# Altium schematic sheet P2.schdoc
size 297 x 209 mm; Symbol: Drawing-Symbol_A4; @Project Name: New Project_2025-09-22_16-04-54; @Page Count: 2; @Update Date: 2026-01-23; @Create Date: 2025-09-24; @Schematic Name: Schematic1; @Page No: 2; @Page Name: P2; Company: EasyEDA.com; Version: V1.0; Page Size: A4; @Create Time: 09:42:08; @Update Time: 20:37:24; Border: 1; Width: 1170; Height: 825; Region Start: 1; X Region Count: 6; Y Region Count: 4; Blade Width: 10; Title Block Position: 3; @Board Name: Board1; Device: Drawing-Symbol_A4
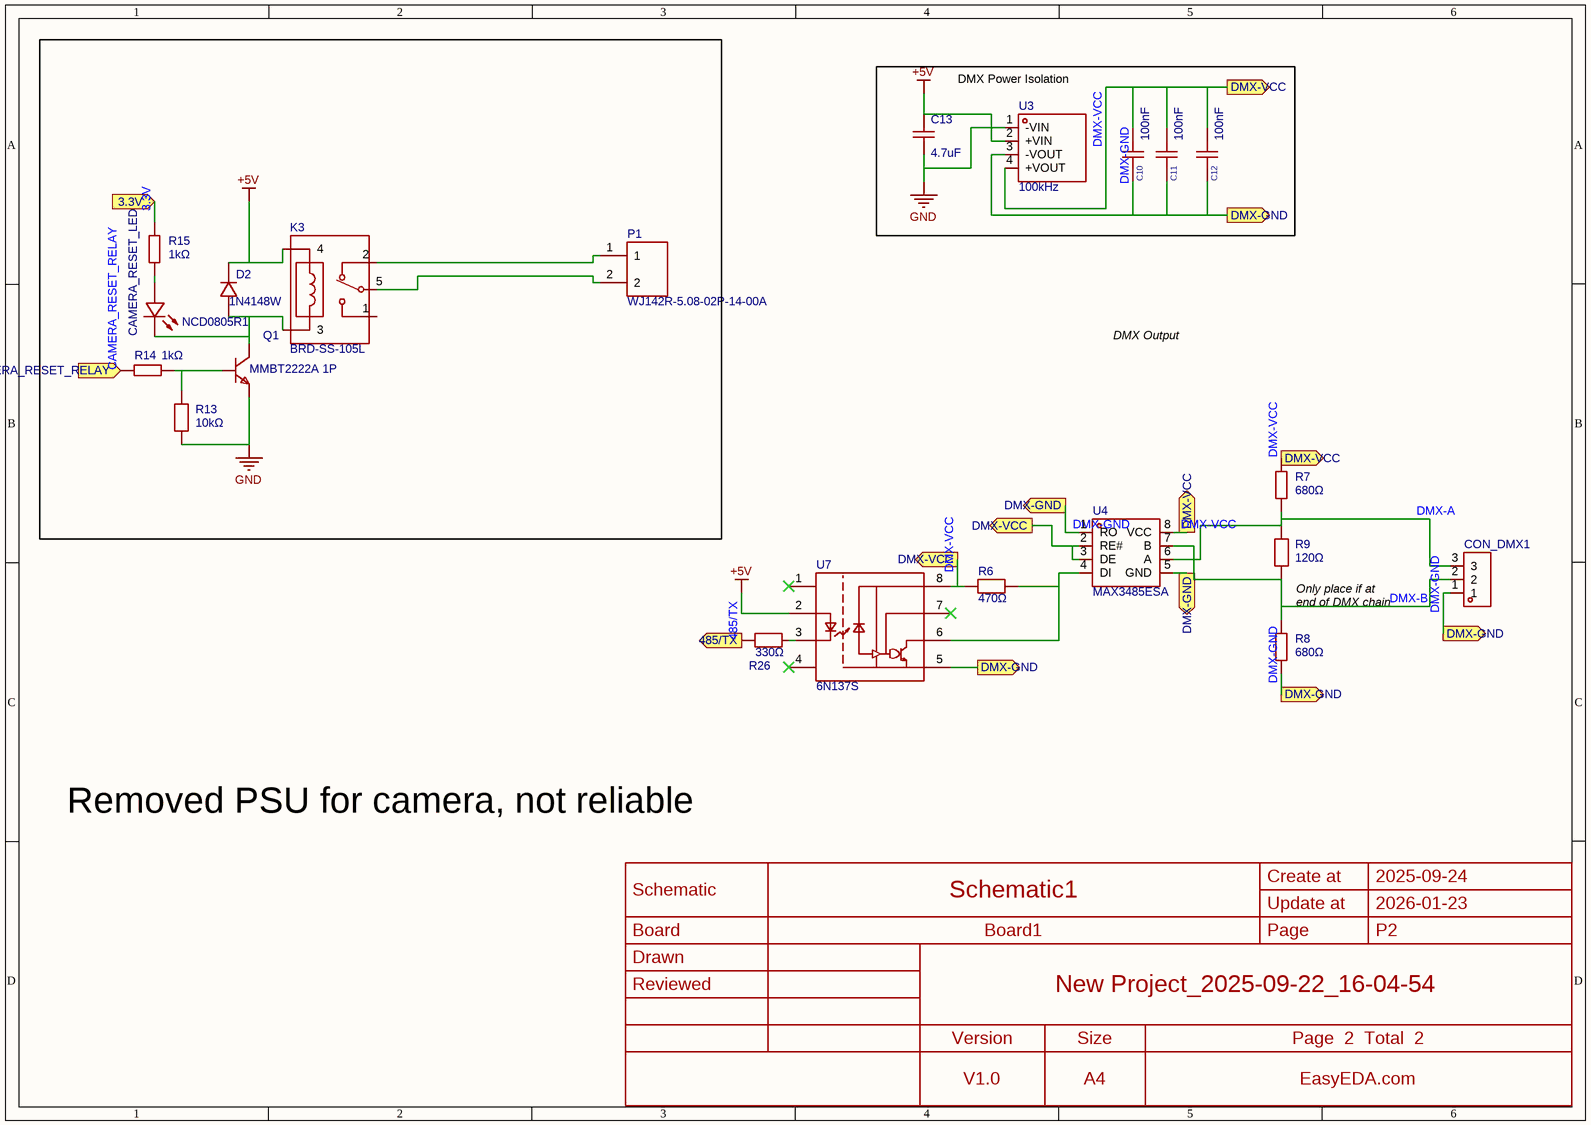
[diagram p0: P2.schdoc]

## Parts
C10  100nF  [C0603]
C11  100nF  [C0603]
C12  100nF  [C0603]
C13  4.7uF  [C0603]
CAMERA_RESET_LED1  NCD0805R1  [LED0805-R-RD]
CON_DMX1  WJ142R-5.08-03P-14-00A  [CONN-TH_3P-P5.08_WJ142R-5.08-3P]  (value not drawn)
D2  1N4148W  [SOD-123F_L2.7-W1.6-LS3.8-RD]
K3  BRD-SS-105L  [RELAY-TH_BRD-SS-1XXL]
P1  WJ142R-5.08-02P-14-00A  [CONN-TH_2P-P5.08_WJ142R-5.08-2P]
Q1  MMBT2222A 1P  [SOT-23-3_L2.9-W1.3-P1.90-LS2.4-BR]
R6  470Ω  [R0603]
R7  680Ω  [R0603]
R8  680Ω  [R0603]
R9  120Ω  [R0603]
R13  10kΩ  [R0603]
R14  1kΩ  [R0603]
R15  1kΩ  [R0603]
R26  330Ω  [R0603]
U3  100kHz  [PWRM-TH_B0505S-1W]
U4  MAX3485ESA  [SOP-8_L4.9-W3.9-P1.27-LS6.0-BL]
U7  6N137S  [SMT-8_L9.7-W6.6-P2.54-LS10.3-BL]

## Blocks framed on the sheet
DMX Power Isolation: C10-C13 U3

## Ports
3.3V (in), 485/TX (out), CAMERA_RESET_RELAY (in), DMX-GND (out), DMX-VCC (out)

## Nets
+5V: C13.1 D2.1(C) K3.4 U3.2(+VIN) U7.2(A)
GND: C13.2 Q1.2(E) R13.1 U3.1(-VIN)
3.3V: R15.2 ; port 3.3V
485/TX: R26.1 ; port 485/TX
CAMERA_RESET_RELAY: R14.1 ; port CAMERA_RESET_RELAY
DMX-A: CON_DMX1.3 R7.1 R9.2 U4.6(A)
DMX-B: CON_DMX1.2 R8.2 R9.1 U4.7(B)
DMX-GND: C10.1 C11.1 C12.1 CON_DMX1.1 R8.1 U3.3(-VOUT) U4.1(RO) U4.5(GND) U7.5(GND) ; port DMX-GND
DMX-VCC: C10.2 C11.2 C12.2 R6.1 R7.2 U3.4(+VOUT) U4.2(RE#) U4.3(DE) U4.8(VCC) U7.8(VCC) ; port DMX-VCC
NetCAMERA_RESET_LED1_1: CAMERA_RESET_LED1.1(+) R15.1
NetCAMERA_RESET_LED1_2: CAMERA_RESET_LED1.2(-) D2.2(A) K3.3 Q1.3(C)
NetK3_2: K3.2 P1.1
NetK3_5: K3.5 P1.2
NetQ1_1: Q1.1(B) R13.2 R14.2
NetR6_2: R6.2 U4.4(DI) U7.6(VO)
NetR26_2: R26.2 U7.3(C)

Not connected (* = marked no-connect by the designer): K3 1; U7 1(NC)* 4(NC)* 7(VE)*

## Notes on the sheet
- DMX Output
- Only place if at
  end of DMX chain
- Removed PSU for camera, not reliable

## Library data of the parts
C10-C12 = CC0603KRX7R9BB104: Capacitance:100nF Tolerance:±10% Tolerance:±10% Voltage Rating:50V Temperature Coefficient:X7R; Manufacturer: YAGEO(国巨); Symbol: CL10B104KB8NNNC; AddInBom: yes; ModelId: 624118aa3cc7497086c383c2d72e0852; ModelName: C0603_L1.6-W0.8-H0.8; ModelTransform: 62.992,31.496,0,0,0,0,0,0,0; Tolerance: ±10%; Voltage Rating: 50V; Temperature Coefficient: X7R
C13 = CL10A475KO8NNNC: Capacitance:4.7uF Tolerance:±10% Tolerance:±10% Voltage Rating:16V Temperature Coefficient:X5R; Manufacturer: SAMSUNG(三星); Symbol: CL10A475KA8NQNC; AddInBom: yes; ModelId: 624118aa3cc7497086c383c2d72e0852; ModelName: C0603_L1.6-W0.8-H0.8; ModelTransform: 62.992,31.496,0,0,0,0,0,0,0; Tolerance: ±10%; Voltage Rating: 16V; Temperature Coefficient: X5R
CAMERA_RESET_LED1 = NCD0805R1_C84256: Lamp Holder Type:- Emitted Color:Red Forward Voltage (VF):1.6V~2.6V Forward Voltage (VF):1.6V~2.6V Power Dissipation:65mW Forward Current:20mA Dominant Wavelength:615nm~630nm Dominant Wavelength:615nm~630nm Peak Wavelength:- Diode Configuration:独立二极管 Lens; Manufacturer: 国星光电; Symbol: FC-2012HRK-620D; AddInBom: yes; ModelId: 167045bb0eae412b9d5564860e113a91; ModelName: LED0805-RD; ModelTransform: 79.527,49.2125,0,0,0,0,0,0,0; Emitted Color: Red; Power Dissipation: 65mW; Forward Current: 20mA; Diode Configuration: 独立二极管; Lens Color: 无色透明透镜; Luminous Intensity: 67mcd~195mcd; Viewing Angle: 130°
CON_DMX1 = WJ142R-5.08-03P-14-00A: Pitch:5.08mm Mounting Type:Through Hole Number of Pins:3P Number of PINs Per Row:3 Number of Rows:1 Current Rating:10A Voltage Rating (Max):300V Wire Gauge - AWG:14~22 Wire Gauge - mm2:1.5 Operating Temperature:-40℃~+105℃ Operating Temperature:-40℃~+105℃; Manufacturer: KANGNEX(康奈克斯电气); Symbol: KF250NH-3.5-3P; AddInBom: yes; ModelId: 8cd8c3ff248846bd841eaf5950ec502b; ModelTransform: 699.9986,555.117,0,0,0,0,50,-58.661,-137.795; Pitch: 5.08mm; Number of PINs Per Row: 3; Current Rating: 10A; Voltage Rating (Max): 300V; Wire Gauge - AWG: 14~22; Wire Gauge - mm2: 1.5
D2 = 1N4148W_C81598: Diode Configuration:Independent Voltage - Forward(Vf@If):1V@50mA Voltage - DC Reverse(Vr):75V Current - Rectified:150mA Pd - Power Dissipation:400mW Reverse Leakage Current (Ir):1uA@75V Reverse Recovery Time (trr):4ns Operating Junction Temperature Range:; Manufacturer: ST(先科); Symbol: 1N4148-C85057; AddInBom: yes; ModelId: 46d11844f5bc46af9e9b7e7acb3962a5; ModelTransform: 149.606,62.992,0,0,0,0,0,0,0; Voltage - DC Reverse(Vr): 75V; Current - Rectified: 150mA; Pd - Power Dissipation: 400mW; Reverse Recovery Time (trr): 4ns; Non-Repetitive Peak Forward Surge Current: 1A
K3 = BRD-SS-105L: Coil Voltage:5V Contact Form:1 Form C: 1C (SPDT-CO) Number of Pins:5 Contact Rating:15A@125VAC；12A@250VAC Switching Voltage(Max):250V@AC Coil Rated Power:360mW Contact Material:Silver Alloy Switching Current(Max):15A Coil Resistance:70Ω Contact Resistance; Manufacturer: QLRELAY(群力); AddInBom: yes; Coil Voltage: 5V; Coil Rated Power: 360mW; Switching Current(Max): 15A; Coil Resistance: 70Ω; Contact Resistance: 100mΩ; Operate Time: 10ms; Release Time: 5ms
P1 = WJ142R-5.08-02P-14-00A: Pitch:5.08mm Mounting Type:Through Hole Number of Pins:2P Number of PINs Per Row:2 Number of Rows:1 Current Rating:10A Voltage Rating (Max):300V Wire Gauge - AWG:14~22 Wire Gauge - mm2:1.5 Operating Temperature:-40℃~+105℃ Operating Temperature:-40℃~+105℃; Manufacturer: KANGNEX(康奈克斯电气); Symbol: WJ142R-5.08-2P-14-00A; AddInBom: yes; ModelId: 9a502304c63443359925f49f0614e344; ModelTransform: 499.999,555.117,0,0,0,0,-52.166,58.858,-137.795; Pitch: 5.08mm; Number of PINs Per Row: 2; Current Rating: 10A; Voltage Rating (Max): 300V; Wire Gauge - AWG: 14~22; Wire Gauge - mm2: 1.5
Q1 = MMBT2222A 1P: type:NPN Current - Collector(Ic):600mA Collector - Emitter Voltage VCEO:40V Pd - Power Dissipation:300mW DC Current Gain:100@150mA,10V DC Current Gain:100@150mA,10V Transition frequency(fT):300MHz Current - Collector Cutoff:10nA Vce Saturation(VCE(sat)):-; Manufacturer: CJ(江苏长电/长晶); AddInBom: yes; ModelId: 62a57c6760504a01965db6419a6d07df; ModelName: SOT-23-3P_L2.9-W1.3-H1.0-LS2.4-P0.95; ModelTransform: 98.425,114.173,0,180,0,0,0.0005,-0.0005,0; type: NPN; Current - Collector(Ic): 600mA; Collector - Emitter Voltage VCEO: 40V; Pd - Power Dissipation: 300mW; Transition frequency(fT): 300MHz; Current - Collector Cutoff: 10nA
R6 = 0603WAF4700T5E: Type:Thick Film Resistor Resistance:470Ω Tolerance:±1% Tolerance:±1% Power(Watts):100mW Voltage-Supply(Max):75V Temperature Coefficient:±100ppm/℃ Temperature Coefficient:±100ppm/℃ Operating Temperature:-55℃~+155℃ Operating Temperature:-55℃~+155℃; Manufacturer: UNI-ROYAL(厚声); Symbol: FRC0603J471 TS; AddInBom: yes; ModelId: 112863783b5b41f1b5254f87eedc7932; ModelTransform: 31.8897,63.7794,0,90,0,0,0,0,0; Tolerance: ±1%; Power(Watts): 100mW; Voltage-Supply(Max): 75V
R7 R8 = 0603WAF6800T5E: Type:Thick Film Resistors Resistance: Tolerance:±1% Tolerance:±1% Power(Watts): Overload Voltage (Max): Temperature Coefficient:±100ppm/℃ Temperature Coefficient:±100ppm/℃ Operating Temperature Range:-55℃~+155℃ Operating Temperature Range:-55℃~+155℃; Manufacturer: UNI-ROYAL(厚声); Symbol: RC0603FR-07680RL; AddInBom: yes; ModelId: 112863783b5b41f1b5254f87eedc7932; ModelTransform: 31.8897,63.7794,0,90,0,0,0,0,0; Tolerance: ±1%
R9 = 0603WAF1200T5E: Type:Thick Film Resistors Resistance: Tolerance:±1% Tolerance:±1% Power(Watts): Overload Voltage (Max): Temperature Coefficient:±100ppm/℃ Temperature Coefficient:±100ppm/℃ Operating Temperature Range:-55℃~+155℃ Operating Temperature Range:-55℃~+155℃; Manufacturer: UNI-ROYAL(厚声); Symbol: FRC0603J121 TS; AddInBom: yes; ModelId: 112863783b5b41f1b5254f87eedc7932; ModelTransform: 31.8897,63.7794,0,90,0,0,0,0,0; Tolerance: ±1%
R13 = 0603WAF1002T5E: Type:Thick Film Resistor Resistance:10kΩ Tolerance:±1% Tolerance:±1% Power(Watts):100mW Voltage-Supply(Max):75V Temperature Coefficient:±100ppm/℃ Temperature Coefficient:±100ppm/℃ Operating Temperature:-55℃~+155℃ Operating Temperature:-55℃~+155℃; Manufacturer: UNI-ROYAL(厚声); Symbol: FRC0603J103TS; AddInBom: yes; ModelId: 112863783b5b41f1b5254f87eedc7932; ModelTransform: 31.8897,63.7794,0,90,0,0,0,0,0; Tolerance: ±1%; Power(Watts): 100mW; Voltage-Supply(Max): 75V
R14 R15 = 0603WAF1001T5E: Type:Thick Film Resistors Resistance:1kΩ Tolerance:±1% Tolerance:±1% Power(Watts): Overload Voltage (Max): Temperature Coefficient:±100ppm/℃ Temperature Coefficient:±100ppm/℃ Operating Temperature Range:-55℃~+155℃ Operating Temperature Range:-55℃~+155℃; Manufacturer: UNI-ROYAL(厚声); AddInBom: yes; ModelId: 112863783b5b41f1b5254f87eedc7932; ModelTransform: 31.8897,63.7794,0,90,0,0,0,0,0; Tolerance: ±1%
R26 = 0603WAF3300T5E: Type:Thick Film Resistors Resistance: Tolerance:±1% Tolerance:±1% Power(Watts): Overload Voltage (Max): Temperature Coefficient:±100ppm/℃ Temperature Coefficient:±100ppm/℃ Operating Temperature Range:-55℃~+155℃ Operating Temperature Range:-55℃~+155℃; Manufacturer: UNI-ROYAL(厚声); Symbol: FRC0603F3300TS; AddInBom: yes; ModelId: 112863783b5b41f1b5254f87eedc7932; ModelTransform: 31.8897,63.7794,0,90,0,0,0,0,0; Tolerance: ±1%
U3 = B0505S-1W_C20617263: Number of Channels:1 Output Power:1W Voltage - Supply:5V Voltage - Supply:5V Conversion Efficiency:78% Conversion Efficiency:78% Output Voltage:5V Output Voltage:5V Output Current(Max):200mA Output Current(Max):200mA Capacitive Load(Max):220uF Isolation V; Manufacturer: ReSine PS(瑞鑫); Symbol: RO-0505S; AddInBom: yes; ModelId: 61e39b78b79f49169cbb099917bebb2a; ModelTransform: 456.692,236.22,0,0,0,0,0.394,81.85,-157.48; Number of Channels: 1; Output Power: 1W; Voltage - Supply: 5V; Conversion Efficiency: 78%; Output Current(Max): 200mA; Capacitive Load(Max): 220uF; Isolation Voltage(Vrms): 1.5kV
U4 = MAX3485ESA: Type:Transceiver Number of Drivers:1 Number of Receivers:1 Voltage - Supply:3V~3.6V Voltage - Supply:3V~3.6V Data Rate:12Mbps Data Rate:12Mbps Number of Nodes:256 Supply Current (Iq):520uA Communication Mode:Half-Duplex; Manufacturer: TWGMC(迪嘉); Symbol: MAX3485ECN; AddInBom: yes; ModelId: 9e479aa4755a4392b89c401224ad1275; ModelName: SOP-8_L4.9-W3.9-P1.27-LS6.0-BL-1; ModelTransform: 192.913,236.22,0,0,0,0,0,0,0; Number of Drivers: 1; Data Rate: 12Mbps; Number of Nodes: 256; Supply Current (Iq): 520uA
U7 = 6N137S_C5123515: Input Type:DC Voltage - Supply:4.5V~5.5V Voltage - Supply:4.5V~5.5V Isolation Voltage(Vrms):2.5kV CMTI(kV/us):10kV/us Data Rate:10Mbps Number of Channels:1 Operating Temperature:-40℃~+85℃ Operating Temperature:-40℃~+85℃ Low level Delay Time:100ns High lev; Manufacturer: UMW(友台半导体); AddInBom: yes; ModelId: 8510953e035d485896759a8421c5bb70; ModelName: SMT-8_L9.7-W6.6-H5.1-P2.54-LS10.3-BL; ModelTransform: 381.889,405.511,0,0,0,0,0,0,0; Input Type: DC; Isolation Voltage(Vrms): 2.5kV; Data Rate: 10Mbps; Number of Channels: 1; Low level Delay Time: 100ns; Input threshold current: 15mA; power dissipation: 100mW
